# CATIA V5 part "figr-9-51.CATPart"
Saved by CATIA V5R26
Part number: Part1
Bounding box of the stored display mesh (mm): x -121 to 121, y -90 to 90, z -40 to 40
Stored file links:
  D:\_Deepak\CATIA\CATIA V5-6R2016_Deepak\Resources\Part files\Partfiles\c09_catia_v5_6r2016_prt\figr-9-51.CATPart
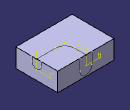
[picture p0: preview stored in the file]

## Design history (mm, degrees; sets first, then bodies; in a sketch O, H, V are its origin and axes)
Body1 (main body)
  Sketch1 on yz-plane, origin (0, 0, 0), H (0, 1, 0), V (0, 0, 1)
    line L1 (-90, 40) -> (90, 40)
    line L2 (90, 40) -> (90, -40)
    line L3 (90, -40) -> (-90, -40)
    line L4 (-90, -40) -> (-90, 40)
    axis line L5 (90, -40) -> (-90, 40)
    horizontal: L1 H, L3 H
    vertical: L2 V, L4 V
    midpoint: O L5
  Pad1: profile Sketch1, direction (1, 0, 0), length 121, mirrored extent
  Sketch2 on face of Pad1, origin (0, 0, 40), H (1, 0, 0), V (0, 1, 0)
    point P1 (121, 0)
    line L1 (121, 0) -> (40.984, 0)
    arc A1 centre (40.984, 40.984) radius 40.984 from (40.984, 0) to (0, 40.984) cw
    line L2 (0, 40.984) -> (0, 90)
    point P5 (0, 90)
    reference projected line E1 (121, 20) -> (121, -20) from edge of Sketch4
    reference projected line E2 (-25.9516, 90) -> (25.9516, 90) from edge of Sketch3
    coincidence: P1 H, P1 E1, P5 E2
    horizontal: L1 H
    tangency: A1 L1, L2 A1
    vertical: L2 V
  Sketch3 on face of Pad1, origin (0, 90, 0), H (-1, 0, 0), V (0, 0, 1)
    line L1 (-25.9516, 40) -> (-25.9516, -8.0968)
    arc A1 centre (0, -8.0968) radius 25.9516 from (-25.9516, -8.0968) to (25.9516, -8.0968) ccw
    point P3 (0, -8.0968)
    line L2 (25.9516, -8.0968) -> (25.9516, 40)
    line L3 (25.9516, 40) -> (-25.9516, 40)
    reference projected line E1 (121, 40) -> (-121, 40) from edge [face of Pad1 | face of Pad1]
    vertical: L1 V, L2 V
    tangency: A1 L1, L2 A1
    horizontal: L3 H
    coincidence: P3 V, L3 E1
  Sketch4 on face of Pad1, origin (121, 0, 0), H (0, 1, 0), V (0, 0, 1)
    line L1 (-20, 40) -> (-20, 21.9917)
    arc A1 centre (0, 21.9917) radius 20 from (-20, 21.9917) to (20, 21.9917) ccw
    point P3 (0, 21.9917)
    line L2 (20, 21.9917) -> (20, 40)
    line L3 (20, 40) -> (-20, 40)
    reference projected line E1 (90, 40) -> (-90, 40) from edge [face of Pad1 | face of Pad1]
    vertical: L1 V, L2 V
    tangency: A1 L1, L2 A1
    horizontal: L3 H
    coincidence: P3 V, L3 E1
